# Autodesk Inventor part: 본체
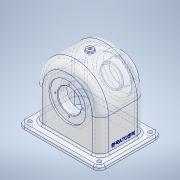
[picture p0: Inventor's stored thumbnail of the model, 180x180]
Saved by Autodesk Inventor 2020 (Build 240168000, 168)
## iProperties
Created: 2022-09
Part Number: 본체
Material: 알루미늄 6061
Document SubType Name: Modeling
Designer: USER
Density: 2.7 g/cm^3
Appearance: 알루미늄 - 평지
Mass: 785.035 g
Surface Area: 1042.06 cm^2
Volume: 290.754 cm^3
Author: USER
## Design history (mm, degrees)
sketch "스케치2"
  geometry: L1 (-57, -64)-(-57, 0); L2 (57, 0)-(57, -64); L3 (57, -64)-(-57, -64); A1 r 57 centre (0, 0) between (57, 0) and (-57, 0); 2 further points
  constraints: 6 end point, 2 point on circle, 1 centre point, 1 coincident, 1 horizontal alignment, 1 midpoint, 1 perpendicular, 1 tangent, 1 vertical, 1 vertical alignment
  dimensions: "d0" = 114 diameter of A1; "d3" = 64 distance from line of point (0, 0) L3
extrude "돌출1" new body sketch "스케치2" distance "d4" = 78; taper "d5" = 0 deg
sketch "스케치3"
  geometry: C1 r 31 at (0, 0); 1 further point
  constraints: 1 centre point, 1 coincident
  dimensions: "d6" = 62 diameter of C1
extrude "돌출2" join sketch "스케치3" distance "d7" = 15; taper "d8" = 0 deg
node "작업 평면1"
sketch "스케치5"
  geometry: L1 (-13, 15)-(127, 15); L2 (127, 15)-(127, -93); L3 (127, -93)-(-13, -93); L4 (-13, -93)-(-13, 15); L5 (0, -78)-(0, 0) reference; L6 (0, 0)-(114, 0) reference; L7 (114, 0)-(114, -78) reference; L8 (114, -78)-(0, -78) reference; 5 further points
  constraints: 8 end point, 4 midpoint, 2 parallel, 1 horizontal, 1 horizontal alignment, 1 perpendicular, 1 vertical alignment
  dimensions: "d12" = 140 distance of L1.start L1.end; "d13" = 108 distance of L1.end L2.end
extrude "돌출4" join sketch "스케치5" distance "d14" = 7; taper "d15" = 0 deg
sketch "스케치4"
  geometry: L1 (-57, -57)-(-57, 0) reference; L2 (57, 0)-(57, -57) reference; L3 (-52, 0)-(-52, -85.984); L4 (52, -79.891)-(52, 0); L5 (-52, -85.984)-(52, -79.891); L6 (57, -57)-(70, -57) reference; L7 (70, -57)-(70, -64) reference; L8 (70, -64)-(-70, -64) reference; L9 (-70, -64)-(-70, -57) reference; L10 (-70, -57)-(-57, -57) reference; A1 r 57 centre (0, 0) between (57, 0) and (-57, 0) reference; A2 r 52 centre (0, 0) between (52, 0) and (-52, 0); 1 further point
  constraints: 7 end point, 2 point on circle, 1 centre point, 1 horizontal alignment, 1 vertical, 1 other
  dimensions: "d9" = 5 radial gap between concentric circles of A1 A2
extrude "돌출3" cut sketch "스케치4" stored distance "d10" = 68; taper "d11" = 0 deg
sketch "스케치6"
  geometry: L1 (0, -13.706)-(0, -110.185); L2 (36.083, -5)-(28, -19); L3 (28, -19)-(20, -19); L4 (20, -19)-(20, -5); L5 (20, -5)-(36.083, -5); L6 (57, -78)-(31, -78) reference; L7 (-31, -93)-(-31, -78) reference; L8 (31, -93)-(-31, -93) reference; L9 (31, -78)-(31, -93) reference; L10 (-31, -78)-(-57, -78) reference; L11 (-57, -78)-(-57, -93) reference; L12 (-57, -93)-(-64, -93) reference; L13 (-64, -93)-(-64, -73) reference; L14 (-64, -73)-(52, -73) reference; L15 (52, -73)-(52, -5) reference; L16 (52, -5)-(-64, -5) reference; L17 (-64, -5)-(-64, 15) reference; L18 (-64, 15)-(-57, 15) reference; L19 (-57, 15)-(-57, 0) reference; L20 (-57, 0)-(57, 0) reference; L21 (57, 0)-(57, -78) reference; 1 further point
  constraints: 10 end point, 2 perpendicular, 1 collinear, 1 horizontal, 1 vertical, 1 vertical alignment
  dimensions: "d16" = 14 distance between parallel lines of L3 L5; "d17" = 56 diameter of L2.end L1; "d18" = 30 deg angle of L4 L2; "d19" = 40 diameter of L4 L1
revolve "회전1" sketch "스케치6" stored, may be unused: angle "d20" = 90 deg
sketch "스케치7"
  geometry: L1 (0, 0)-(0, -128.844); L2 (0, 0)-(-57, 0) reference; L3 (0, 0)-(32, 0); L4 (32, 0)-(32, -3); L5 (32, -3)-(0, -3); L6 (0, -3)-(0, 0); L7 (0, 0)-(0, -78) reference; L8 (20, -3)-(0, -3); L9 (0, -3)-(0, -19); L10 (0, -19)-(20, -19); L11 (20, -19)-(20, -3); L12 (17.5, -73)-(0, -73); L13 (0, -73)-(0, -77); L14 (17.5, -77)-(17.5, -73); L15 (20, -77)-(17.5, -77); L16 (0, -77)-(0, -93); L17 (0, -93)-(20, -93); L18 (20, -93)-(20, -77); L19 (57, -78)-(31, -78) reference; L20 (-31, -93)-(-31, -78) reference; L21 (31, -93)-(-31, -93) reference; L22 (31, -78)-(31, -93) reference; L23 (-31, -78)-(-57, -78) reference; L24 (-57, -78)-(-57, -93) reference; L25 (-57, -93)-(-64, -93) reference; L26 (-64, -93)-(-64, -73) reference; L27 (-64, -73)-(52, -73) reference; L28 (52, -73)-(52, -5) reference; L29 (52, -5)-(36.083, -5) reference; L30 (36.083, -5)-(28, -19) reference; L31 (28, -19)-(20, -19) reference; L32 (20, -19)-(20, -5) reference; L33 (20, -5)-(-20, -5) reference; L34 (-20, -5)-(-20, -19) reference; L35 (-20, -19)-(-28, -19) reference; L36 (-28, -19)-(-36.083, -5) reference; L37 (-36.083, -5)-(-64, -5) reference; L38 (-64, -5)-(-64, 15) reference; L39 (-64, 15)-(-57, 15) reference; L40 (-57, 15)-(-57, 0) reference; L41 (-57, 0)-(57, 0) reference; L42 (57, 0)-(57, -78) reference; L43 (20, -77)-(17.5, -77); 4 further points
  constraints: 34 end point, 8 parallel, 4 collinear, 4 horizontal, 4 perpendicular, 4 point on line, 1 coincident, 1 vertical
  dimensions: "d21" = 40 diameter of L18 L1; "d22" = 35 diameter of L14 L1; "d23" = 16 distance of L17.end L15.start; "d24" = 16 distance of L10.end L8.start; "d25" = 40 diameter of L11 L1; "d26" = 64 diameter of L4 L1
revolve "회전2" sketch "스케치7" stored, may be unused: angle "d27" = 90 deg
node "작업 평면2"
sketch "스케치8"
  geometry: L1 (13, -15)-(13, -93) reference; C1 r 6 at (70, -54); 2 further points
  constraints: 1 centre point, 1 horizontal alignment, 1 midpoint, 1 vertical alignment
  dimensions: "d29" = 12 diameter of C1
extrude "돌출5" join sketch "스케치8" stored distance "d30" = 7; taper "d31" = 0 deg
sketch "스케치9"
  geometry: C1 r 6 at (0, 0) reference; 2 further points
  constraints: 1 coincident
hole "구멍1" sketch "스케치9" at (0, 0) diameter "d32" = 5.1881; stored, may be unused: countersink angle "d36" = 90 deg, drill point angle "d38" = 118 deg; dims "d33" = 12, "d34" = 4, "d35" = 2, "d37" = 16
sketch "스케치10"
  geometry: A1 r 24 centre (0, 0) between (0, 24) and (-24, 0); 3 further points
  constraints: 4 point on circle, 2 horizontal alignment, 2 vertical alignment, 1 centre point, 1 coincident
  dimensions: "d39" = 48 diameter of A1
sketch "스케치11"
  geometry: A1 r 24 centre (0, 0) between (0, 24) and (-24, 0); 3 further points
  constraints: 4 point on circle, 2 horizontal alignment, 2 vertical alignment, 1 centre point, 1 coincident
  dimensions: "d40" = 48 diameter of A1
hole "구멍2" sketch "스케치10" diameter "d41" = 2.459; stored, may be unused: countersink angle "d45" = 90 deg, drill point angle "d47" = 118 deg; dims "d42" = 7, "d43" = 4, "d44" = 2, "d46" = 9
hole "구멍3" sketch "스케치11" diameter "d48" = 2.459; stored, may be unused: countersink angle "d52" = 90 deg, drill point angle "d54" = 118 deg; dims "d49" = 7, "d50" = 4, "d51" = 2, "d53" = 9
fillet "모깎기1" dims "d55" = 10, "d56" = 14
sketch "스케치12"
  geometry: A1 r 10 centre (-3, -5) between (-13, -5) and (-3, -15) reference; A2 r 10 centre (-3, 83) between (-3, 93) and (-13, 83) reference; A3 r 10 centre (117, 83) between (127, 83) and (117, 93) reference; A4 r 10 centre (117, -5) between (117, -15) and (127, -5) reference; 1 further point
hole "구멍4" sketch "스케치12" at (-3, -5), (117, -5), (117, 83), (-3, 83) diameter "d57" = 6.6; stored, may be unused: countersink angle "d61" = 90 deg, drill point angle "d63" = 118 deg; dims "d58" = 7, "d59" = 4, "d60" = 2, "d62" = 9
sketch "스케치13"
  geometry: L1 (69, -7)-(-19, -7) reference; L2 (-14, 57)-(-14, 0) reference; 1 further point
  constraints: 1 other
  dimensions: "d64" = 17 distance from line of point (25, 10) L1; "d65" = 39 distance from line of L2 point (25, 10)
feature "엠보싱1" sketch "스케치13" dims "d0" = 114, "d3" = 64, "d66" = 0.5, "d67" = 0
fillet "모깎기2" dims "d68" = 1
fillet "모깎기3" dims "d69" = 0.6
chamfer "모따기1" distance "d70" = 1; stored, may be unused: second distance "d71" = 2, angle "d72" = 45 deg
fillet "모깎기4" dims "d73" = 9
fillet "모깎기5" dims "d74" = 3
node "솔리드1"
node "절단 모서리 투영1"
node "절단 모서리 투영2"
node "절단 모서리 투영3"
node "절단 모서리 투영4"
feature "A9D066F2-1C7D-4E18-AEED-F7BC21143FA4" dims "d57" = 6.6, "d58" = 7, "d59" = 4, "d60" = 2, "d61" = 90 deg, "d62" = 9, "d63" = 118 deg
other parameters: "d28" = -124
